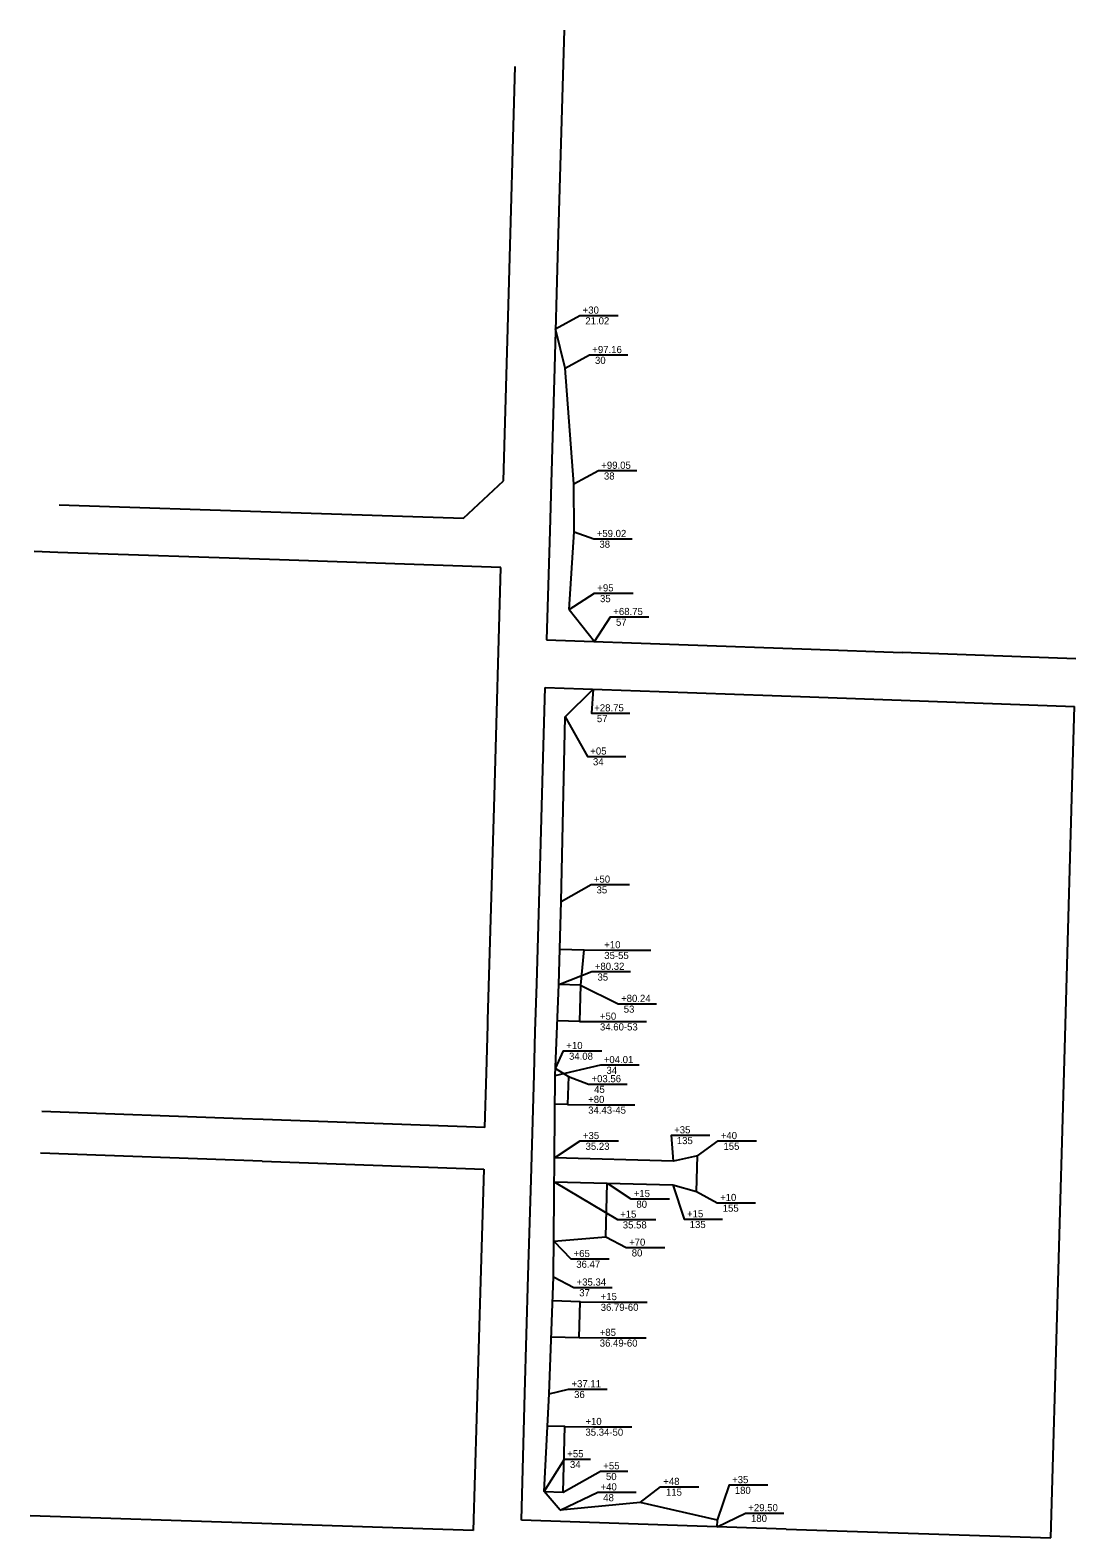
# Model space of a CAD drawing. Extents: x 979729 to 993523, y 1834148 to 1845433.
# Drawn here: x 992130 to 993007, y 1844168 to 1845433 of the extents above; entities that cross this region are included whole.
import ezdxf

# ---------------------------------------------------------------- set-up
doc = ezdxf.new("R2010")
doc.units = 0
for name, color, linetype in [('51', 7, 'Continuous'), ('53', 7, 'Continuous'), ('R_Draft', 7, 'Continuous'), ('S_EXIST_ROW', 7, 'Continuous')]:
    doc.layers.add(name, color=color, linetype=linetype)

msp = doc.modelspace()

# ---------------------------------------------------------------- linework, layer by layer
at = {"layer": '51'}
for p, q in [((992578.6, 1845149.1), (992570.5, 1845182.2)), ((992586, 1845052.1), (992578.6, 1845149.1)), ((992586.3, 1845012.1), (992586, 1845052.1)), ((992581.9, 1844946.9), (992586.3, 1845012.1)), ((992581.9, 1844946.9), (992603.2, 1844920.1)), ((992578.5, 1844857), (992602.1, 1844880.1)), ((992575.3, 1844702), (992578.5, 1844857)), ((992573.4, 1844632.3), (992575.3, 1844702)), ((992570.3, 1844556.1), (992573.4, 1844632.3)), ((992568.7, 1844387.4), (992570.3, 1844556.1)), ((992565.1, 1844289.2), (992568.7, 1844387.4)), ((992560.9, 1844207.2), (992565.1, 1844289.2)), ((992574.5, 1844191.8), (992560.9, 1844207.2)), ((992641.6, 1844198), (992574.5, 1844191.8)), ((992706.3, 1844183.2), (992641.6, 1844198)), ((992706.1, 1844177.8), (992706.3, 1844183.2))]:
    msp.add_line(p, q, dxfattribs=at)
at = {"layer": '53'}
msp.add_line((992591.4, 1844631.8), (992573.4, 1844632.3), dxfattribs=at)
for points in [[(992574.2, 1844662), (992594.2, 1844661.5), (992591.4, 1844631.8), (992590.6, 1844601.5), (992572.2, 1844602)], [(992570.6, 1844562.1), (992581.3, 1844555.3), (992580.7, 1844531.8), (992570.1, 1844532.1)], [(992569.5, 1844467.1), (992668.9, 1844464.4), (992688.7, 1844458.8), (992689.5, 1844488.8), (992669.4, 1844484.4), (992569.7, 1844487.1)], [(992569, 1844417.1), (992612.7, 1844420.9), (992613.9, 1844465.9)], [(992566.9, 1844337.1), (992590.4, 1844336.4), (992591.2, 1844366.4), (992568, 1844367.1)], [(992560.9, 1844207.2), (992576.9, 1844206.8), (992578.4, 1844261.7), (992563.7, 1844262.1)]]:
    msp.add_lwpolyline(points, dxfattribs=at)
at = {"layer": 'R_Draft'}
for p, q in [((992596.9, 1845193.4), (992623.1, 1845193.4)), ((992605, 1845160.3), (992631.2, 1845160.3)), ((992612.5, 1845063.3), (992638.7, 1845063.3)), ((992608.7, 1845006.1), (992634.9, 1845006.1)), ((992609.3, 1844960.5), (992635.5, 1844960.5)), ((992622.7, 1844940.7), (992648.9, 1844940.7)), ((992606.6, 1844859.9), (992632.8, 1844859.9)), ((992603.4, 1844823.7), (992629.6, 1844823.7)), ((992606.3, 1844716.3), (992632.5, 1844716.3)), ((992624.2, 1844661.3), (992650.4, 1844661.3)), ((992607.1, 1844643.2), (992633.3, 1844643.2)), ((992629.1, 1844616.3), (992655.3, 1844616.3)), ((992620.6, 1844601.4), (992646.8, 1844601.4)), ((992583.2, 1844576.8), (992609.4, 1844576.8)), ((992614.6, 1844565), (992640.8, 1844565)), ((992604.3, 1844549), (992630.5, 1844549)), ((992610.7, 1844531.6), (992636.9, 1844531.6)), ((992673.7, 1844506.1), (992699.9, 1844506.1)), ((992597.1, 1844501.3), (992623.3, 1844501.3)), ((992712.8, 1844501.3), (992739, 1844501.3)), ((992639.8, 1844452.7), (992666, 1844452.7)), ((992712.1, 1844449.4), (992738.3, 1844449.4)), ((992628.4, 1844435.4), (992654.6, 1844435.4)), ((992684.4, 1844435.7), (992710.6, 1844435.7)), ((992589.4, 1844402.4), (992615.6, 1844402.4)), ((992635.9, 1844411.9), (992662.1, 1844411.9)), ((992591.8, 1844378.5), (992618, 1844378.5)), ((992621.2, 1844366.2), (992647.4, 1844366.2)), ((992620.4, 1844336.3), (992646.6, 1844336.3)), ((992587.5, 1844293.2), (992613.7, 1844293.2)), ((992608.4, 1844261.6), (992634.6, 1844261.6)), ((992584.1, 1844234.5), (992599.8, 1844234.5)), ((992614.2, 1844224.4), (992631.2, 1844224.4)), ((992722.3, 1844212.8), (992748.5, 1844212.8)), ((992611.9, 1844206.7), (992638.1, 1844206.7)), ((992664.5, 1844211.3), (992690.7, 1844211.3)), ((992735.8, 1844189.3), (992762, 1844189.3))]:
    msp.add_line(p, q, dxfattribs=at)
for points in [[(992570.5, 1845182.2), (992590.9, 1845193.4), (992596.9, 1845193.4)], [(992578.6, 1845149.1), (992599, 1845160.3), (992605, 1845160.3)], [(992586, 1845052.1), (992606.5, 1845063.3), (992612.5, 1845063.3)], [(992586.3, 1845012.1), (992602.7, 1845006.1), (992608.7, 1845006.1)], [(992581.9, 1844946.9), (992603.3, 1844960.5), (992609.3, 1844960.5)], [(992603.2, 1844920.1), (992616.7, 1844940.7), (992622.7, 1844940.7)], [(992602.1, 1844880.1), (992600.6, 1844859.9), (992606.6, 1844859.9)], [(992578.5, 1844857), (992597.4, 1844823.7), (992603.4, 1844823.7)], [(992575.3, 1844702), (992600.3, 1844716.3), (992606.3, 1844716.3)], [(992594.2, 1844661.5), (992618.2, 1844661.3), (992624.2, 1844661.3)], [(992573.4, 1844632.3), (992601.1, 1844643.2), (992607.1, 1844643.2)], [(992591.4, 1844631.8), (992623.1, 1844616.3), (992629.1, 1844616.3)], [(992590.6, 1844601.5), (992614.6, 1844601.4), (992620.6, 1844601.4)], [(992570.6, 1844562.1), (992577.2, 1844576.8), (992583.2, 1844576.8)], [(992570.3, 1844556.1), (992608.6, 1844565), (992614.6, 1844565)], [(992581.3, 1844555.3), (992598.3, 1844549), (992604.3, 1844549)], [(992580.7, 1844531.8), (992604.7, 1844531.6), (992610.7, 1844531.6)], [(992669.4, 1844484.4), (992667.7, 1844506.1), (992673.7, 1844506.1)], [(992569.7, 1844487.1), (992591.1, 1844501.3), (992597.1, 1844501.3)], [(992689.5, 1844488.8), (992706.8, 1844501.3), (992712.8, 1844501.3)], [(992569.5, 1844467.1), (992622.4, 1844435.4), (992628.4, 1844435.4)], [(992613.9, 1844465.9), (992633.8, 1844452.7), (992639.8, 1844452.7)], [(992668.9, 1844464.4), (992678.4, 1844435.7), (992684.4, 1844435.7)], [(992688.7, 1844458.8), (992706.1, 1844449.4), (992712.1, 1844449.4)], [(992569, 1844417.1), (992583.4, 1844402.4), (992589.4, 1844402.4)], [(992612.7, 1844420.9), (992629.9, 1844411.9), (992635.9, 1844411.9)], [(992568.7, 1844387.4), (992585.8, 1844378.5), (992591.8, 1844378.5)], [(992591.2, 1844366.4), (992615.2, 1844366.2), (992621.2, 1844366.2)], [(992590.4, 1844336.4), (992614.4, 1844336.3), (992620.4, 1844336.3)], [(992565.1, 1844289.2), (992581.5, 1844293.2), (992587.5, 1844293.2)], [(992578.4, 1844261.7), (992602.4, 1844261.6), (992608.4, 1844261.6)], [(992560.9, 1844207.2), (992578.1, 1844234.5), (992584.1, 1844234.5)], [(992576.9, 1844206.8), (992608.2, 1844224.4), (992614.2, 1844224.4)], [(992706.3, 1844183.2), (992716.3, 1844212.8), (992722.3, 1844212.8)], [(992574.5, 1844191.8), (992605.9, 1844206.7), (992611.9, 1844206.7)], [(992641.6, 1844198), (992658.5, 1844211.3), (992664.5, 1844211.3)], [(992706.1, 1844177.8), (992729.8, 1844189.3), (992735.8, 1844189.3)]]:
    msp.add_lwpolyline(points, dxfattribs=at)
at = {"layer": 'S_EXIST_ROW'}
for p, q in [((992577.7, 1845432.6), (992572.2, 1845242.7)), ((992531.4, 1845212.1), (992536.8, 1845402.1)), ((992572.2, 1845242.7), (992569.6, 1845149.5)), ((992526.8, 1845054.8), (992531.4, 1845212.1)), ((992569.6, 1845149.5), (992566.8, 1845052.8)), ((992493.5, 1845023.3), (992526.8, 1845054.8)), ((992566.8, 1845052.8), (992565.7, 1845012.8)), ((992154.3, 1845034.7), (992340.1, 1845028.5)), ((992340.1, 1845028.5), (992493.5, 1845023.3)), ((992565.7, 1845012.8), (992563, 1844921.5)), ((992153.2, 1844994.7), (992133.4, 1844995.4)), ((992339, 1844988.5), (992153.2, 1844994.7)), ((992524.8, 1844982.2), (992339, 1844988.5)), ((992519.3, 1844790.3), (992524.8, 1844982.2)), ((992563, 1844921.5), (992784.9, 1844913.6)), ((992784.9, 1844913.6), (992861.3, 1844910.8)), ((993006.8, 1844905.6), (992861.3, 1844910.8)), ((992560.2, 1844822.9), (992561.9, 1844881.5)), ((992561.9, 1844881.5), (992657.5, 1844878.1)), ((992657.5, 1844878.1), (992783.8, 1844873.6)), ((992783.8, 1844873.6), (993005.7, 1844865.6)), ((993004, 1844808.7), (993005.7, 1844865.6)), ((992557.6, 1844730.7), (992560.2, 1844822.9)), ((992998.6, 1844618.8), (993004, 1844808.7)), ((992513.9, 1844602.8), (992519.3, 1844790.3)), ((992554.8, 1844632.9), (992557.6, 1844730.7)), ((992553.6, 1844592.9), (992554.8, 1844632.9)), ((992997.5, 1844578.8), (992998.6, 1844618.8)), ((992512.6, 1844558.4), (992513.8, 1844598.4)), ((992513.8, 1844598.4), (992513.9, 1844602.8)), ((992552.6, 1844557.1), (992553.6, 1844592.9)), ((992991.6, 1844373.6), (992997.5, 1844578.8)), ((992511.3, 1844512.6), (992512.6, 1844558.4)), ((992550.1, 1844469), (992552.6, 1844557.1)), ((992307.7, 1844519.9), (992139.7, 1844525.9)), ((992325.5, 1844519.2), (992307.7, 1844519.9)), ((992511.3, 1844512.6), (992325.5, 1844519.2)), ((992324.5, 1844484.3), (992138.7, 1844490.9)), ((992324.5, 1844484.3), (992394.3, 1844481.8)), ((992394.3, 1844481.8), (992510.3, 1844477.6)), ((992510.3, 1844477.6), (992507.1, 1844365.1)), ((992547.7, 1844388.1), (992550.1, 1844469)), ((992544.9, 1844289.8), (992547.7, 1844388.1)), ((992507.1, 1844365.1), (992504.3, 1844268.5)), ((992985.7, 1844168.5), (992991.6, 1844373.6)), ((992541.9, 1844183.2), (992544.9, 1844289.8)), ((992504.3, 1844268.5), (992501.6, 1844174.5)), ((992315.8, 1844180.7), (992130, 1844186.8)), ((992501.6, 1844174.5), (992315.8, 1844180.7)), ((992664.3, 1844179.1), (992541.9, 1844183.2)), ((992763.8, 1844175.8), (992664.3, 1844179.1)), ((992763.8, 1844175.8), (992985.7, 1844168.5))]:
    msp.add_line(p, q, dxfattribs=at)

# ---------------------------------------------------------------- texts
at = {"layer": 'R_Draft'}
for s, p in [('+30', (992593.3, 1845194.9)), (' 21.02', (992593.3, 1845185.9)), ('+97.16', (992601.4, 1845161.8)), (' 30', (992601.4, 1845152.8)), ('+99.05', (992608.9, 1845064.8)), (' 38', (992608.9, 1845055.8)), ('+59.02', (992605.1, 1845007.6)), (' 38', (992605.1, 1844998.6)), ('+95', (992605.6, 1844962)), (' 35', (992605.6, 1844953)), ('+68.75', (992619, 1844942.2)), (' 57', (992619, 1844933.2)), ('+28.75', (992603, 1844861.4)), (' 57', (992603, 1844852.4)), ('+05', (992599.7, 1844825.2)), (' 34', (992599.7, 1844816.2)), ('+50', (992602.7, 1844717.8)), (' 35', (992602.7, 1844708.8)), ('+10', (992611.4, 1844662.8)), ('35-55', (992611.4, 1844653.8)), ('+80.32', (992603.5, 1844644.7)), (' 35', (992603.5, 1844635.7)), ('+80.24', (992625.5, 1844617.8)), ('+50', (992607.8, 1844602.9)), (' 53', (992625.5, 1844608.8)), ('34.60-53', (992607.8, 1844593.9)), ('+10', (992579.6, 1844578.3)), (' 34.08', (992579.6, 1844569.3)), ('+04.01', (992611, 1844566.5)), ('+03.56', (992600.7, 1844550.5)), (' 34', (992611, 1844557.5)), (' 45', (992600.7, 1844541.5)), ('34.43-45', (992597.9, 1844524.1)), ('+80', (992597.9, 1844533.1)), ('+35', (992593.5, 1844502.8)), ('+35', (992670, 1844507.6)), (' 135', (992670, 1844498.6)), ('+40', (992709.1, 1844502.8)), (' 35.23', (992593.5, 1844493.8)), (' 155', (992709.1, 1844493.8)), ('+15', (992636.1, 1844454.2)), ('+10', (992708.5, 1844450.9)), ('+15', (992624.7, 1844436.9)), (' 80', (992636.1, 1844445.2)), ('+15', (992680.8, 1844437.2)), (' 155', (992708.5, 1844441.9)), (' 35.58', (992624.7, 1844427.9)), (' 135', (992680.8, 1844428.2)), ('+70', (992632.2, 1844413.4)), ('+65', (992585.7, 1844403.9)), (' 36.47', (992585.7, 1844394.9)), (' 80', (992632.2, 1844404.4)), ('+35.34', (992588.2, 1844380)), (' 37', (992588.2, 1844371)), ('36.79-60', (992608.4, 1844358.8)), ('+15', (992608.4, 1844367.8)), ('+85', (992607.6, 1844337.8)), ('36.49-60', (992607.6, 1844328.8)), ('+37.11', (992583.9, 1844294.7)), (' 36', (992583.9, 1844285.7)), ('+10', (992595.6, 1844263.1)), ('35.34-50', (992595.6, 1844254.1)), ('+55', (992580.4, 1844236)), (' 34', (992580.4, 1844227)), ('+55', (992610.6, 1844225.9)), ('+40', (992608.3, 1844208.2)), (' 50', (992610.6, 1844216.9)), ('+48', (992660.9, 1844212.8)), ('+35', (992718.6, 1844214.3)), (' 48', (992608.3, 1844199.2)), (' 115', (992660.9, 1844203.8)), (' 180', (992718.6, 1844205.3)), ('+29.50', (992732.2, 1844190.8)), (' 180', (992732.2, 1844181.8))]:
    msp.add_text(s, height=6, rotation=360, dxfattribs=at).set_placement(p)

doc.saveas('drawing.dxf')
